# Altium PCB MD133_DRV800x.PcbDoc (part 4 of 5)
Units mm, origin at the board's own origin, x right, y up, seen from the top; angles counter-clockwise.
Board outline 152.66 x 101.89 mm, 4 copper layers (Top Layer, Mid-Layer 1, Mid-Layer 2, Bottom Layer), stack 2.355 mm thick; 306 components, 166 nets, 1010 pads, 1623 vias.
Unrouted connection lines stored in the file: 4.
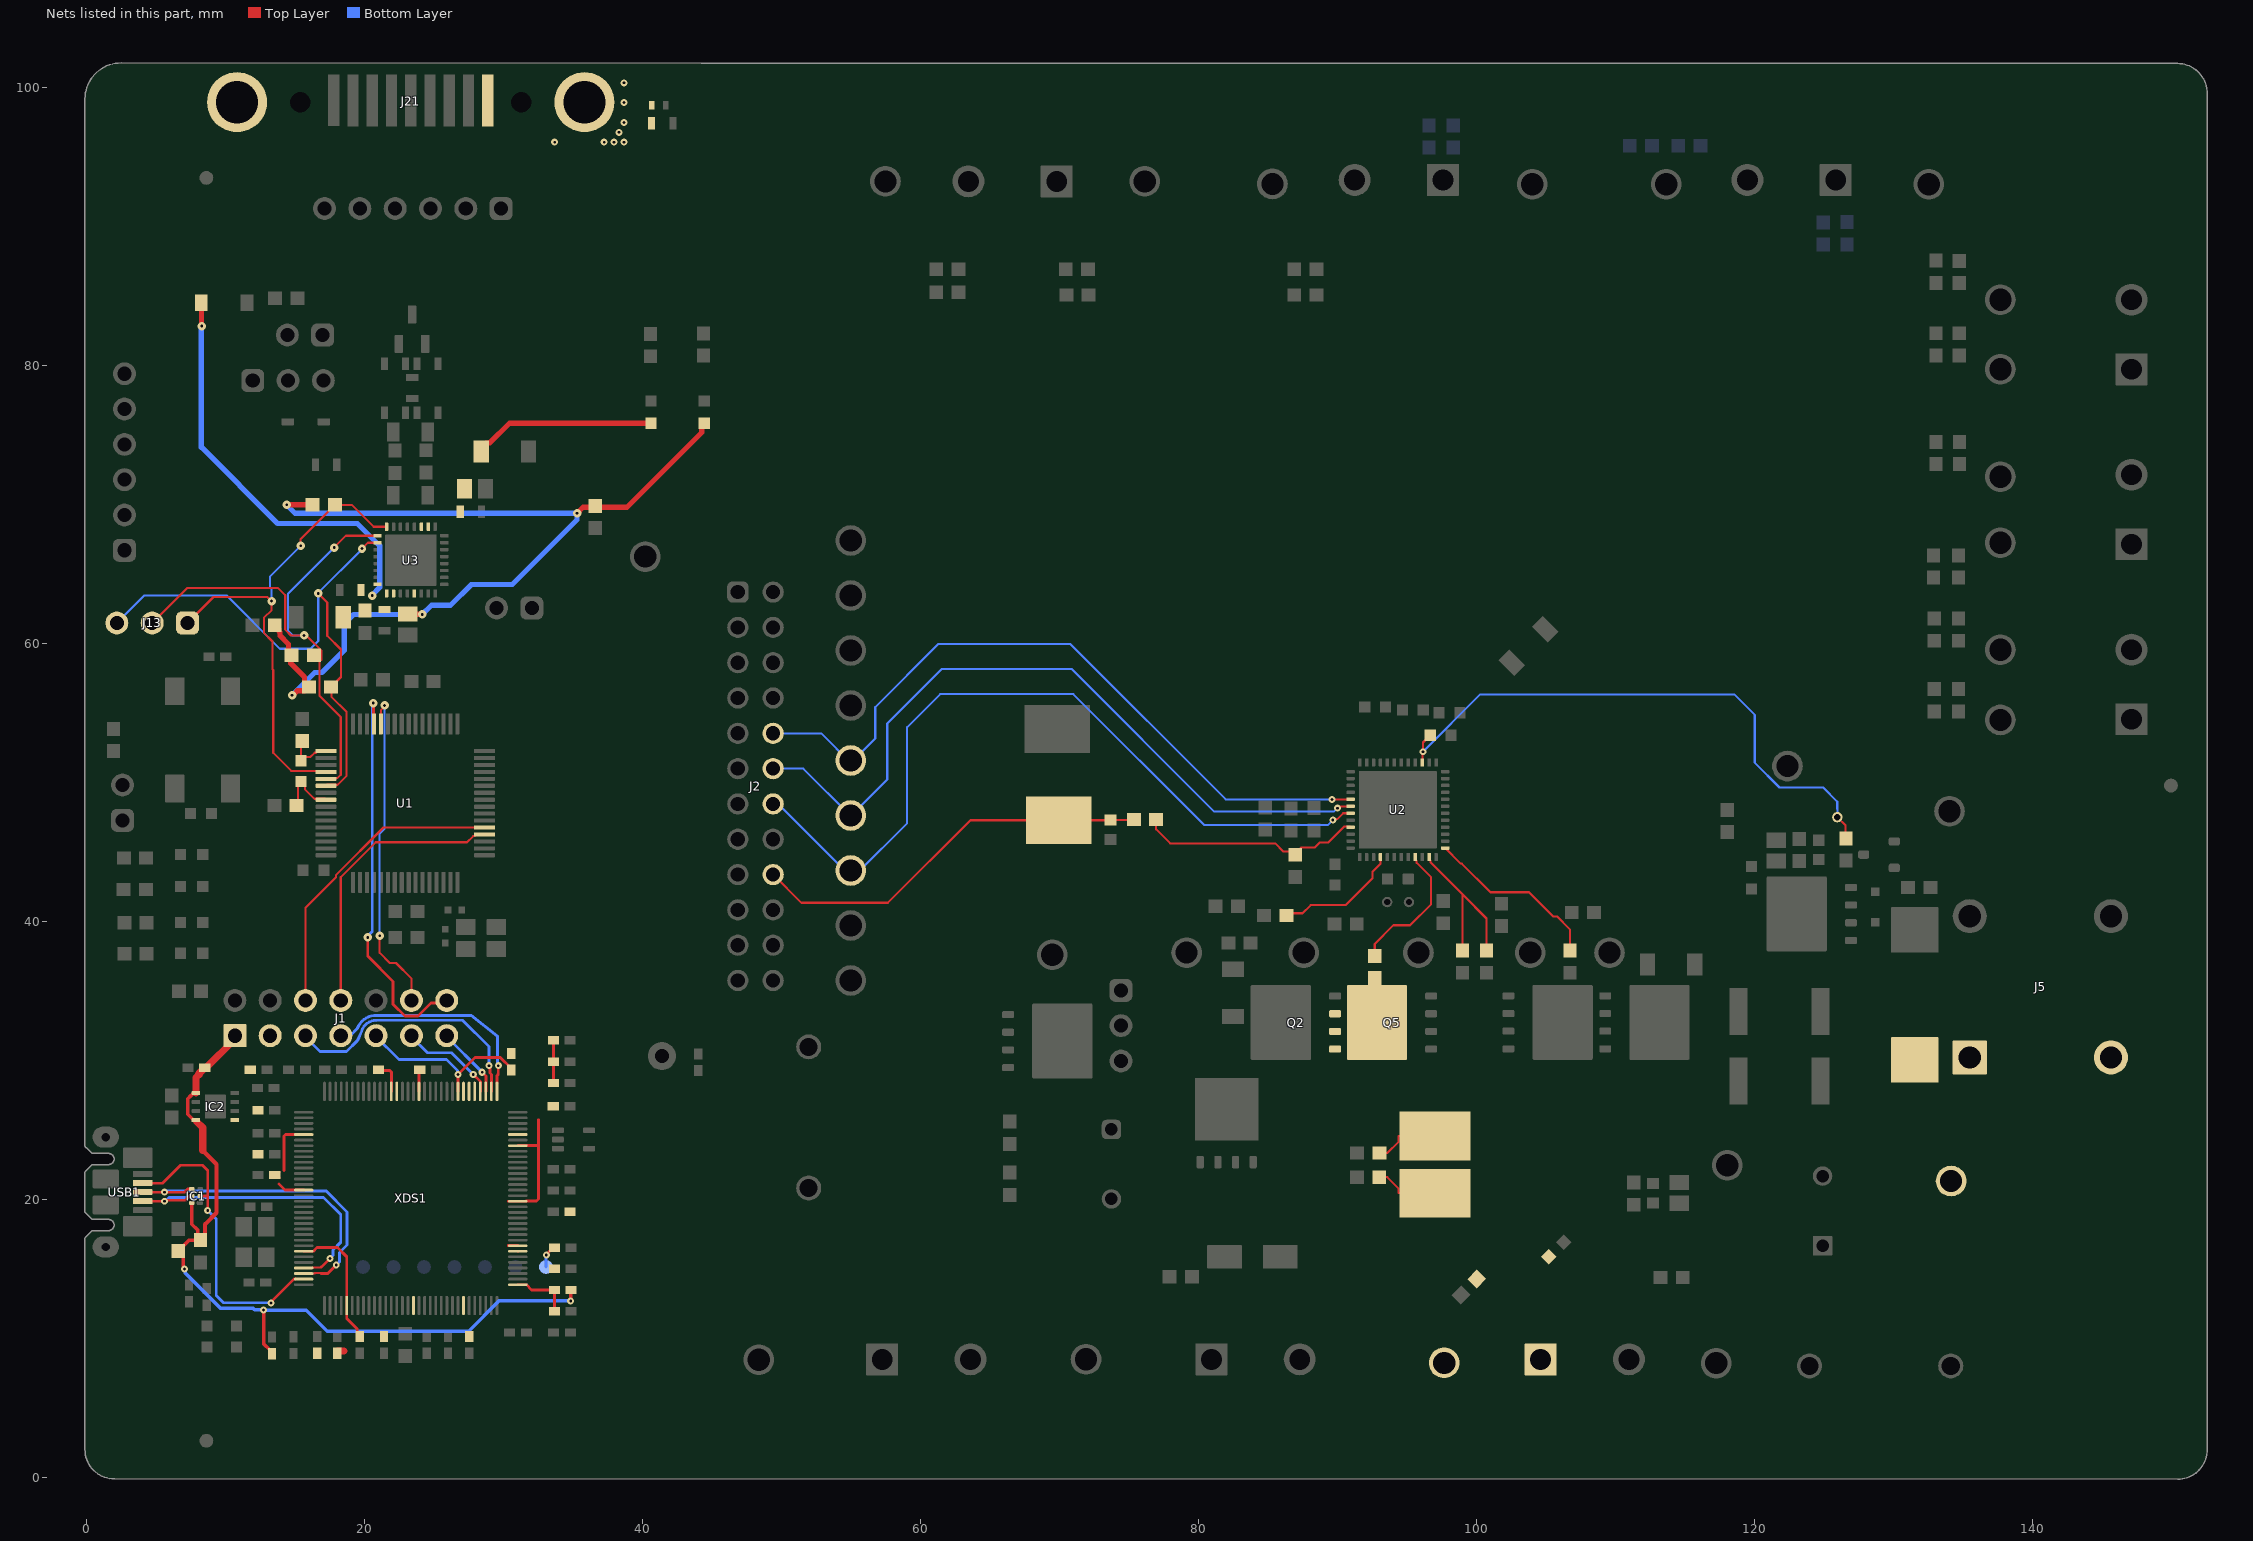
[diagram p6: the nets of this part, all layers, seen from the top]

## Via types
v1: diameter 0.5, hole 0.2, Top Layer to Bottom Layer, tented both sides, 1483 vias
v2: diameter 0.61, hole 0.2, Top Layer to Bottom Layer, tented both sides, 58 vias
v3: diameter 0.508, hole 0.203, Top Layer to Bottom Layer, tented both sides, 46 vias
v4: diameter 0.5, hole 0.2, Top Layer to Bottom Layer, 16 vias
v5: diameter 0.711, hole 0.356, Top Layer to Bottom Layer, tented both sides, 10 vias
v6: diameter 0.61, hole 0.203, Top Layer to Bottom Layer, tented both sides, 5 vias
v7: diameter 5, hole 4.3, Top Layer to Bottom Layer, 3 vias
v8: diameter 5, hole 4.5, Top Layer to Bottom Layer, 1 vias
v9: diameter 0.864, hole 0.406, Top Layer to Bottom Layer, tented both sides, 1 vias

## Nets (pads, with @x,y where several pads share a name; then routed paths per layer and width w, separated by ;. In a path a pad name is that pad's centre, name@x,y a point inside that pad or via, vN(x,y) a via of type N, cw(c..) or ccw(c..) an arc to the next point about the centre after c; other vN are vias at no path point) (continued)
SCLK: J2.14 TP15.1 U2.19 | length 58
  Top Layer w0.152: v1(89.637,47.303) 89.704,47.37 89.967,47.37 90.386,47.789 U2.19@90.915,47.789
  Bottom Layer w0.152: J2.14@49.378,48.461 49.75,48.461 50.113,48.098 50.115,48.098 54.679,43.534 54.958,43.534 55.014,43.59 TP15.1@55.014,43.987 ; TP15.1@54.958,43.59 TP15.1@54.958,43.987 ; TP15.1@55.014,43.534 55.467,43.534 59.013,47.079 59.013,53.984 61.392,56.363 70.973,56.363 80.402,46.934 89.268,46.934 v1(89.637,47.303)
SDI: J2.10 TP13.1 U2.17 | length 51.9
  Top Layer w0.152: v1(89.569,48.789) U2.17@90.915,48.789
  Bottom Layer w0.152: J2.10@49.378,53.541 52.825,53.541 54.958,51.408 56.723,53.172 56.723,55.427 61.265,59.969 70.743,59.969 81.924,48.789 v1(89.569,48.789)
SDO: J2.12 TP14.1 U2.18 | length 54.1
  Top Layer w0.152: v1(89.97,48.154) 90.064,48.154 90.199,48.289 U2.18@90.915,48.289
  Bottom Layer w0.152: J2.12@49.378,51.001 51.555,51.001 54.958,47.598 57.582,50.221 57.582,54.247 61.501,58.166 70.858,58.166 81.115,47.909 89.707,47.909 89.951,48.154 v1(89.97,48.154)
SH1: R37.2 U2.37 | length 13
  Top Layer w0.152: U2.37@97.715,45.289 98.84,44.164 98.921,44.164 100.979,42.106 103.753,42.106 105.498,40.36 105.768,40.36 106.689,39.44 R37.2@106.689,37.815
SH2: R38.2 U2.33 | length 10.2
  Top Layer w0.152: R38.2@92.65,37.242 92.65,38.387 93.995,39.733 95.187,39.733 96.707,41.253 96.707,43.188 95.664,44.232 95.664,44.365 95.565,44.464 U2.33@95.565,44.639
SH_HS: R45.2 U2.28 | length 9.1
  Top Layer w0.152: R45.2@86.294,40.437 86.453,40.596 87.454,40.596 88.043,41.184 90.55,41.184 92.489,43.122 92.489,43.574 93.065,44.15 U2.28@93.065,44.639
SHIELD_GND: C85.1 J21.5 J21.10 J21.11 R72.2
  other v1: 33.665,96.064 37.221,96.064 37.932,96.064 38.644,96.064 38.288,96.775 38.644,97.487 38.644,98.909 38.644,100.331
SL: R41.2 R42.2 U2.35 | length 12.9
  Top Layer w0.152: U2.35@96.565,44.639 96.565,44.464 96.662,44.367 96.662,44.254 98.974,41.942 ; R41.2@98.974,37.815 98.974,41.942 ; R42.2@100.694,37.815 100.694,40.222 98.974,41.942 ; R42.2@100.844,37.99 100.869,37.99 R42.2@101.006,38.127
  Top Layer w0.254: R41.2@99.141,38.106 R41.2@99.141,38.131
SNS_N: C40.1 C42.2 J4.1 R36.1 R58.2 TP24.1 | length 4.8
  Top Layer w0.152: R58.2@93.038,21.678 R58.2@92.974,21.614 93.551,21.614 94.375,20.789 94.375,20.468 R36.1@97.001,20.468
SNS_P: Q2.1 Q2.2 Q2.3 Q5.5 Q5.6 Q5.7 Q5.8 Q5.9@92.81,32.734 R36.2 R38.1 R52.2 | length 4.8
  Top Layer w0.152: R52.2@92.984,23.353 93.56,23.353 94.375,24.167 94.375,24.578 R36.2@97.001,24.578
SO: C63.1 J2.18 R53.1 TP17.1 | length 29.4
  Top Layer w0.152: J2.18@49.378,43.381 51.408,41.35 57.632,41.35 63.57,47.289 TP17.1@69.912,47.289 C63.1@73.626,47.289 ; C63.1@73.636,47.3 73.64,47.303 R53.1@74.867,47.303
  Bottom Layer w0.152: J2.18@49.378,42.783 J2.18@49.378,43.381
SO_P: C86.1 R53.2 U2.21 | length 16.1
  Top Layer w0.152: R53.2@76.928,47.344 76.928,46.642 77.944,45.627 85.494,45.627 86.088,45.032 87.07,45.032 87.369,45.331 88.338,45.331 88.691,45.684 89.309,45.684 90.476,46.85 90.602,46.85 90.614,46.838 90.866,46.838 U2.21@90.915,46.789
SWCLK: J1.14 U1.13 | length 29.1
  Top Layer w0.203: v2(20.217,38.862) 20.217,37.525 22.044,35.699 22.044,34.051 22.892,33.203 23.825,33.203 24.768,34.147 25.715,34.147 J1.14@25.898,34.33 ; v2(20.607,55.718) 20.635,55.691 20.635,54.241 U1.13@20.662,54.214
  Bottom Layer w0.203: v2(20.217,38.862) 20.217,38.972 20.539,39.293 20.539,55.65 v2(20.607,55.718) ; J1.14@25.898,34.33 J1.14@26.101,34.533
SWDIO: J1.12 U1.12 | length 24
  Top Layer w0.152: v2(21.073,38.972) 21.073,37.752 21.805,37.02 22.25,37.02 23.358,35.912 J1.12@23.358,34.33 ; U1.12@21.162,54.214 21.164,54.216 21.164,55.193 21.426,55.455 v2(21.426,55.551)
  Bottom Layer w0.152: v2(21.073,38.972) 21.073,46.321 21.426,46.673 v2(21.426,55.551)
UART1_RX: J1.6 U1.53 | length 22
  Top Layer w0.152: J1.6@15.738,34.33 15.738,40.984 17.926,43.171 17.926,43.338 21.352,46.764 U1.53@28.612,46.764
UART1_TX: J1.8 U1.52 | length 20.5
  Top Layer w0.152: J1.8@18.278,34.33 18.278,43.192 20.79,45.703 27.357,45.703 27.796,46.143 27.891,46.143 28.012,46.264 U1.52@28.612,46.264
VBAT: F1.2 J5.1 TP21.1
VBUS_DETECT: R1.2 R3.2 XDS1.1 | length 4.3
  Top Layer w0.203: XDS1.1@31.007,13.88 31.623,13.88 32.004,13.499 R1.2@33.644,13.499 R3.2@33.644,11.976
VCC1: C75.1 D6.2 R21.2 R43.2 R67.2 R73.2 R74.2 U3.13 | length 70.5
  Top Layer w0.381: R21.2@13.423,61.286 13.573,61.286 13.833,61.026 13.833,60.872 13.902,60.803 13.902,60.565 14.52,59.947 14.52,59.377 R73.2@14.67,59.226 ; v2(14.39,69.975) R74.2@16.252,69.975 ; R73.2@14.745,59.151 R73.2@14.67,59.226 ; v2(14.768,56.283) 14.83,56.283 15.142,56.594 15.669,56.594 15.903,56.829 15.903,56.879 15.669,57.113 15.669,57.588 14.67,58.587 R73.2@14.67,59.226 ; C75.1@23.108,62.118 23.122,62.104 24.118,62.104 v2(24.131,62.09) ; v2(35.277,69.364) 35.713,69.8 38.866,69.8 44.243,75.177 44.243,75.671 D6.2@44.42,75.847
  Bottom Layer w0.381: v2(14.39,69.975) 15.002,69.364 v2(35.277,69.364) 35.262,69.349 35.262,68.902 30.613,64.253 27.668,64.253 26.171,62.756 24.797,62.756 v2(24.131,62.09) 19.199,62.09 18.517,61.407 18.517,59.507 16.926,57.917 16.403,57.917 v2(14.768,56.283)
VCC2: C78.1 C79.1 C83.1 D7.2 U3.26 U3.27 | length 13.2
  Top Layer w0.381: C78.1@28.378,73.81 28.378,74.059 28.737,74.419 28.987,74.419 30.415,75.847 D7.2@40.604,75.847
VCP: C46.1 R32.1 TP30.1 U2.3 | length 42
  Top Layer w0.152: U2.3@96.065,51.439 96.092,51.466 96.092,52.189 v1(96.12,52.216) 96.12,52.878 C46.1@96.647,53.405 ; TP30.1@125.927,47.506 126.521,46.912 R32.1@126.521,45.826
  Bottom Layer w0.152: v1(96.12,52.216) 100.247,56.343 118.51,56.343 119.986,54.867 119.986,51.432 121.772,49.646 124.905,49.646 125.927,48.624 TP30.1@125.927,47.506
VREF_N: C27.1 R27.2 U1.17 | length 3.3
  Top Layer w0.152: R27.2@15.391,52.814 15.428,52.776 C27.1@15.428,51.564 15.71,51.846 16.099,51.846 16.396,52.143 16.491,52.143 16.612,52.264 U1.17@17.212,52.264
VREF_P: C27.2 R26.2 U1.24 | length 3.9
  Top Layer w0.152: R26.2@15.19,48.764 15.19,49.826 C27.2@15.428,50.064 15.69,49.802 15.69,49.525 16.377,48.838 17.138,48.838 U1.24@17.212,48.764
VSUP: C74.1 C76.1 C77.1 D8.2 R64.1 U3.8 U3.9 U3.10 | length 30
  Top Layer w0.381: D8.2@8.248,84.513 8.265,84.497 8.265,82.855 v2(8.281,82.838)
  Bottom Layer w0.381: v2(8.281,82.838) 8.248,82.806 8.248,74.125 13.733,68.64 19.463,68.64 21.073,67.03 21.073,64.036 20.545,63.508 v2(20.545,63.446)
WAKE1: J13.3 R43.1 U1.22 U3.2 | length 42.7
  Top Layer w0.152: v2(16.652,63.603) 17.302,62.953 17.302,60.56 18.292,59.57 18.292,57.593 18.002,57.302 18.002,57.277 17.603,56.879 17.603,56.175 18.701,55.077 18.701,50.492 18.048,49.838 17.286,49.838 U1.22@17.212,49.764 ; v2(19.802,66.834) 20.221,67.253 U3.2@20.92,67.253
  Bottom Layer w0.152: J13.3@2.169,61.476 4.154,63.461 10.057,63.461 13.892,59.626 16.095,59.626 16.652,60.183 v2(16.652,63.603) 16.652,63.643 19.802,66.793 v2(19.802,66.834)
WAKE2: J13.2 R73.1 U1.21 U3.1 | length 39.8
  Top Layer w0.152: J13.2@4.709,61.476 7.214,63.982 13.772,63.982 14.279,63.475 14.279,60.998 14.697,60.581 v2(15.636,60.581) 15.724,60.493 15.878,60.493 16.895,59.476 16.895,58.826 ; R73.1@16.745,59.151 16.745,56.238 18.273,54.71 18.273,50.563 18.048,50.338 17.286,50.338 U1.21@17.212,50.264 ; v2(17.812,66.901) 17.812,66.922 18.642,67.753 U3.1@20.92,67.753
  Bottom Layer w0.152: v2(15.636,60.581) 14.778,60.581 14.778,60.61 14.49,60.898 14.49,63.6 17.79,66.901 v2(17.812,66.901)
WAKE3: J13.1 R74.1 U1.20 U3.32 | length 36
  Top Layer w0.152: J13.1@7.249,61.476 9.121,63.348 12.984,63.348 13.277,63.055 v2(13.302,63.055) 13.302,62.405 12.747,61.85 12.747,60.771 13.369,60.149 13.369,58.162 13.423,58.108 13.423,52.131 14.716,50.838 17.138,50.838 U1.20@17.212,50.764 ; v2(15.391,67.03) 15.391,67.515 17.428,69.553 17.428,69.578 17.827,69.977 19.072,69.977 20.645,68.403 U3.32@21.57,68.403
  Bottom Layer w0.152: v2(13.302,63.055) 13.302,63.948 13.19,64.06 13.19,64.829 v2(15.391,67.03)
XDS_ID: IC1.2 USB1.4 XDS1.95 | length 21.8
  Top Layer w0.203: USB1.4@4.03,21.195 4.045,21.18 5.455,21.18 6.743,22.468 8.337,22.468 8.702,22.103 8.702,20.258 ; IC1.2@8.164,20.258 8.702,20.258 ; v3(8.702,19.217) 8.702,20.258 ; v3(13.249,12.562) 13.288,12.601 13.288,12.661 14.905,14.279 XDS1.95@15.009,14.279
  Bottom Layer w0.203: v3(8.702,19.217) 9.32,18.599 9.32,13.095 9.837,12.578 13.233,12.578 v3(13.249,12.562)
XDS_RESET_OUT: J1.9 R4.1 XDS1.40 | length 13.2
  Top Layer w0.203: v3(26.717,29.002) 27.93,30.215 29.749,30.215 30.545,29.419 R4.1@30.545,29.319 ; XDS1.40@26.718,27.789 v3@26.718,29.002
  Bottom Layer w0.203: J1.9@20.789,31.741 22.457,30.074 25.891,30.074 26.678,29.286 26.678,29.041 v3(26.717,29.002)
XDS_RXD: J1.7 XDS1.33 | length 17.2
  Top Layer w0.203: XDS1.33@29.507,28.379 29.507,28.912 29.607,29.011 v3(29.607,29.631)
  Bottom Layer w0.203: J1.7@18.273,31.815 18.964,31.815 19.471,32.323 ; v3(29.607,29.631) 29.548,29.689 29.548,31.745 27.632,33.25 20.666,33.25 20.522,33.22 ; 19.471,32.322 cw(c20.813,31.815) 20.269,33.143 ; 19.471,32.323 cw(c20.813,31.815) 19.477,32.337 cw(c20.813,31.815) 20.269,33.143 ; 20.269,33.143 20.273,33.144 20.322,33.165 ; 20.322,33.165 cw(c20.4,32.977) 20.352,33.174 ; 20.322,33.165 cw(c20.4,32.977) 20.352,33.174 ; 20.352,33.174 20.395,33.188 ; 20.395,33.188 cw(c20.813,31.815) 20.522,33.22 ; 20.395,33.188 cw(c20.813,31.815) 20.522,33.22
XDS_TCK_SWDCLK: J1.13 XDS1.35 | length 5.1
  Top Layer w0.203: v3(28.45,29.16) 28.719,28.891 XDS1.35@28.719,27.788
  Bottom Layer w0.203: J1.13@25.869,31.741 v3(28.45,29.16)
XDS_TDI: XDS1.38
XDS_TDO_SWO: XDS1.37
XDS_TMS_SWDIO: J1.11 XDS1.36 | length 7
  Top Layer w0.203: v3(27.805,29.002) 28.317,28.49 28.317,27.79 XDS1.36@28.319,27.788
  Bottom Layer w0.203: J1.11@23.329,31.741 24.51,30.56 26.248,30.56 v3(27.805,29.002)
XDS_TXD: J1.5 XDS1.34 | length 20.2
  Top Layer w0.203: v3(28.946,29.631) 29.005,29.572 29.005,29.109 29.119,28.994 XDS1.34@29.119,27.788
  Bottom Layer w0.203: J1.5@15.709,31.741 16.788,30.662 18.696,30.662 19.459,31.426 19.519,31.485 19.781,32.129 ; v3(28.946,29.631) 28.946,31 27.052,32.894 20.813,32.894 ; 19.781,32.129 cw(c20.813,31.815) 20.813,32.894 ; 19.781,32.129 cw(c20.813,31.815) 20.813,32.894
XDS_USB_D_N: IC1.5 USB1.2 XDS1.93 | length 22.5
  Top Layer w0.152: XDS1.93@15.607,15.087 16.215,15.087 16.253,15.124 16.842,15.124 16.868,15.15
  Top Layer w0.203: USB1.2@4.184,19.88 5.593,19.88 v1(5.594,19.879) 5.668,19.953 7.104,19.953 7.409,20.258 IC1.5@7.564,20.258 ; 16.868,15.15 16.878,15.15 v1(17.491,15.763)
  Bottom Layer w0.203: v1(5.594,19.879) 5.654,19.879 5.932,20.157 17.043,20.157 18.271,18.929 18.271,16.927 17.726,16.382 17.726,15.998 v1(17.491,15.763)
XDS_USB_D_P: IC1.4 USB1.3 XDS1.94 | length 24
  Top Layer w0.152: XDS1.94@15.607,14.68 16.384,14.68 16.421,14.718 16.842,14.718 16.868,14.693
  Top Layer w0.203: USB1.3@4.184,20.53 v1(5.594,20.531) v1(5.594,20.531) 7.036,20.531 7.263,20.758 IC1.4@7.564,20.758 ; 16.868,14.693 17.343,14.693 v1(17.952,15.302)
  Bottom Layer w0.203: v1(5.594,20.531) 5.676,20.614 17.232,20.614 18.728,19.118 18.728,16.738 18.183,16.193 18.183,15.533 v1(17.952,15.302)
XDS_VBUS: C1.1 C3.1 IC1.6 IC2.5 IC2.8 J1.1 R1.1 R5.2 R13.1 | length 58.3
  Top Layer w0.254: v3@6.93,15.166 6.93,15.94 R5.2@6.582,16.288 6.582,16.313 7.357,17.088 C1.1@8.169,17.088 ; IC1.6@7.553,19.726 7.553,18.238 7.971,17.82 7.971,17.461 C1.1@8.33,17.461 ; IC2.8@7.654,25.749 7.274,26.129 7.274,27.262 7.467,27.455 7.493,27.455 7.708,27.671 IC2.5@7.853,27.671 ; v3(12.716,12.054) 12.748,12.022 12.748,9.593 13.155,9.187 13.155,9.082 R13.1@13.327,8.909 ; v3(34.814,12.714) 34.814,13.469 R1.1@34.844,13.499
  Top Layer w0.305: C1.1@8.177,17.109 8.504,17.436 8.504,18.219 9.337,19.052 9.337,22.544 8.347,23.535
  Top Layer w0.508: IC2.5@7.853,27.671 7.853,28.77 8.096,29.013 8.096,29.088 8.344,29.336 8.344,29.436 8.39,29.482 8.59,29.482 10.629,31.521 J1.1@10.629,31.741 ; IC2.8@7.899,25.622 8.347,25.174 8.347,23.535
  Bottom Layer w0.254: v3@7.001,15.051 7.075,14.977 7.075,14.727 9.605,12.197 11.954,12.197 12.071,12.079 12.69,12.079 12.741,12.029 15.797,12.029 17.295,10.53 27.473,10.53 29.657,12.714 v3(34.814,12.714)
  other v3: 7.026,15
XDS_VCC: C4.1 C5.1 C6.1 C7.1 C8.1 C9.1 C10.1 C13.1 C14.1 IC2.1 J1.3 R4.2 R7.1 R8.1 R9.2 R10.2 R11.2 R12.2 R14.2 R17.2 R18.2 TP7.1 XDS1.7 XDS1.8 XDS1.16 XDS1.26 XDS1.28 XDS1.39 XDS1.47 XDS1.51 XDS1.52 XDS1.69 XDS1.79 XDS1.90 XDS1.101 XDS1.113 XDS1.122 | length 35.7
  Top Layer w0.203: C5.1@13.529,21.772 C5.1@13.629,21.772 ; 13.827,21.128 14.267,20.688 XDS1.79@15.619,20.688 ; C5.1@13.827,21.574 C5.1@13.629,21.772 ; C5.1@13.827,21.971 C5.1@13.629,21.772 ; 14.183,22.09 14.183,24.561 14.302,24.68 XDS1.69@15.009,24.68 ; XDS1.90@15.607,16.28 16.308,16.28 16.577,16.55 18.05,16.55 18.707,15.892 XDS1.101@18.707,12.38 18.707,11.447 19.459,10.696 19.459,10.328 C9.1@19.637,10.149 ; C7.1@20.942,29.482 21.14,29.283 21.798,29.283 21.917,29.164 21.917,27.79 XDS1.52@21.919,27.788 ; XDS1.47@23.907,27.78 23.907,29.287 C6.1@23.957,29.336 ; C4.1@27.519,10.149 C4.1@27.519,10.249 ; XDS1.8@30.317,16.69 31.017,16.69 XDS1.8@31.019,16.688 ; XDS1.16@30.317,19.886 31.613,19.886 31.617,19.89 32.336,19.89 32.489,20.043 32.489,25.743 ; R4.2@30.418,30.392 R4.2@30.545,30.519 ; XDS1.7@31.017,16.286 XDS1.7@31.019,16.288 ; XDS1.26@31.019,23.888 31.615,23.888 31.617,23.89 32.489,23.89 ; v3(33.061,16.016) 33.061,16.062 33.544,16.545 C13.1@33.644,16.545 ; C14.1@33.456,26.709 C14.1@33.556,26.709 ; R11.2@33.568,31.452 R10.2@33.568,29.919 R9.2@33.568,28.386 R9.2@33.668,28.386
  Top Layer w0.508: R8.1@18.011,8.949 18.011,9.049 18.057,9.095 18.509,9.095 ; C9.1@19.637,10.049 C9.1@19.637,10.149
  Bottom Layer w0.203: TP7.1@33.036,15.153 33.048,15.165 33.048,16.004 v3(33.061,16.016)
pads on no net: FID1.1 FID2.1 FID3.1 H1.0 H2.0 H3.0 H4.0 IC2.2 IC2.3 IC2.6 IC2.7 IC3.2 IC3.4 IC3.5 J21.1 J21.4 J21.9 J21.MH Q2.9@85.213,31.404 Q2.9@85.213,32.734 Q2.9@85.213,34.064 Q2.9@86.228,32.734 Q2.9@86.363,31.404 Q2.9@86.363,32.734 Q2.9@86.363,34.064 Q2.9@87.513,31.404 Q2.9@87.513,32.734 Q2.9@87.513,34.064 Q2.9@87.808,30.361 Q2.9@87.808,35.106 Q3.9@111.224,30.377 Q3.9@111.224,35.122 Q3.9@111.519,31.42 Q3.9@111.519,32.75 Q3.9@111.519,34.08 Q3.9@112.669,31.42 Q3.9@112.669,32.75 Q3.9@112.669,34.08 Q3.9@112.804,32.75 Q3.9@113.819,31.42 Q3.9@113.819,32.75 Q3.9@113.819,34.08 Q4.9@122.326,39.218 Q4.9@122.326,40.548 Q4.9@122.326,41.878 Q4.9@123.341,40.548 Q4.9@123.476,39.218 Q4.9@123.476,40.548 Q4.9@123.476,41.878 Q4.9@124.626,39.218 Q4.9@124.626,40.548 Q4.9@124.626,41.878 Q4.9@124.921,38.176 Q4.9@124.921,42.921 Q5.9@92.125,31.404 Q5.9@92.125,32.734 Q5.9@92.125,34.064 Q5.9@93.14,32.734 Q5.9@93.275,31.404 Q5.9@93.275,32.734 Q5.9@93.275,34.064 Q5.9@94.72,30.361 Q5.9@94.72,35.106 Q5.9@94.425,31.404 Q5.9@94.425,32.734 Q5.9@94.425,34.064 Q6.9@104.257,30.377 Q6.9@104.257,35.122 Q6.9@104.552,31.42 Q6.9@104.552,32.75 Q6.9@104.552,34.08 Q6.9@105.702,31.42 Q6.9@105.702,32.75 Q6.9@105.702,34.08 Q6.9@105.837,32.75 Q6.9@106.852,31.42 Q6.9@106.852,32.75 Q6.9@106.852,34.08 Q7.9@80.556,25.112 Q7.9@80.556,26.892 Q7.9@82.006,25.112 Q7.9@82.006,26.042 Q7.9@82.006,26.892 Q7.9@83.456,25.112 Q7.9@83.456,26.892 Q8.9@68.27,29.031 Q8.9@68.27,33.776 Q8.9@68.565,30.074 Q8.9@68.565,31.404 Q8.9@68.565,32.734 Q8.9@69.85,31.404 Q8.9@69.715,30.074 Q8.9@69.715,31.404 Q8.9@69.715,32.734 Q8.9@70.865,30.074 Q8.9@70.865,31.404 Q8.9@70.865,32.734 SH-J1.0 SH-J2.0 SH-J3.0 SH-J4.0 SH-J5.0 SH-J6.0 SH-J7.0 SH-J8.0 SH-J9.0 SH-J10.0 SH-J11.0 SH-J12.0 SH-J13.0 SH-J14.0 SH-J15.0 SH-J16.0 SH-J17.0 SH-J18.0 SH-J19.0 SH-J20.0 SH-J21.0 U1.2 U1.7 U1.11 U1.15 U1.18 U1.19 U1.23 U1.25 U1.28 U1.31 U1.33 U1.34 U1.36 U1.37 U1.39 U1.42 U1.44 U1.47 U1.49 U1.50 U1.51 U1.55 U1.62 U1.63 U1.64 U3.3 U3.11 U3.12 XDS1.2 XDS1.5 XDS1.6 XDS1.11 XDS1.12 XDS1.13 XDS1.14 XDS1.15 XDS1.18 XDS1.19 XDS1.20 XDS1.21 XDS1.22 XDS1.23 XDS1.24 XDS1.25 XDS1.27 XDS1.29 XDS1.30 XDS1.31 XDS1.32 XDS1.41 XDS1.43 XDS1.44 XDS1.45 XDS1.46 XDS1.49 XDS1.50 XDS1.53 XDS1.54 XDS1.56 XDS1.57 XDS1.65 XDS1.67 XDS1.71 XDS1.72 XDS1.73 XDS1.74 XDS1.75 XDS1.76 XDS1.77 XDS1.78 XDS1.81 XDS1.82 XDS1.83 XDS1.84 XDS1.85 XDS1.86 XDS1.91 XDS1.92 XDS1.102 XDS1.103 XDS1.104 XDS1.105 XDS1.106 XDS1.107 XDS1.108 XDS1.109 XDS1.110 XDS1.111 XDS1.112 XDS1.116 XDS1.117 XDS1.118 XDS1.119 XDS1.121 XDS1.123 XDS1.124 XDS1.125 XDS1.126 XDS1.127 XDS1.128
copper on no net:
  other v3: 16.754,14.111 16.729,15.864 6.645,19.445 6.645,21.503

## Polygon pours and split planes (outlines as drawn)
ECDRV on Top Layer "TOP_LAYER_ECDRV_P352" (solid, remove dead copper, pour order 352): 67.095,24.741 65.715,24.741 65.715,21.392 65.771,21.336 65.811,21.376 66.966,21.376 66.966,24.613
GND on Top Layer "TOP_LAYER_GND_P366" (solid, remove dead copper, pour order 366): 0,101.6 0,0 152.4,0 152.4,101.6
OUT5 on Top Layer "TOP_LAYER_OUT5_P325" (solid, remove dead copper, pour order 325): 91.141,54.91 91.284,54.767 91.63,54.767 92.208,54.189 93.275,53.122 93.275,51.057 93.269,51.063 92.733,51.063 92.733,52.278 91.505,53.506 90.594,53.506 87.757,56.343 87.757,91.066 86.754,92.069 86.659,91.973 84.125,91.973 84.125,94.38 84.22,94.475 91.707,94.475 92.461,93.721 92.461,92.461 91.141,91.141
PVDD on Top Layer "TOP_LAYER_PVDD_P053" (solid, remove dead copper, pour order 330): 120.396,27.078 120.41,27.092 120.41,35.464 120.396,36.905 120.396,42.843 101.327,61.911 94.365,61.911 93.866,61.911 92.741,60.786 92.741,54.235 93.457,53.519 93.457,51.057 93.735,51.057 94.565,51.887 94.565,56.134 98.79,56.134 98.79,54.515 96.32,52.044 96.32,51.093 96.33,51.083 96.344,51.097 96.843,51.097 96.843,51.827 97.13,52.114 98.417,52.114 99.246,52.943 100.272,52.943 102.226,54.897 102.226,54.911 102.85,55.535 103.493,55.535 104.524,54.504 104.524,52.193 101.734,49.402 97.358,49.402 97.358,49.316 97.411,49.263 97.411,47.855 104.016,47.855 113.716,38.156 113.741,36.633 112.966,35.858 110.381,35.858 110.381,20.586 120.396,20.586
OUT7 on Top Layer "TOP_LAYER_OUT7_P350" (solid, remove dead copper, pour order 350): 132.361,86.487 148.209,86.487 148.463,86.233 148.463,83.533 136.722,83.533 135.051,85.205 132.385,85.205
OUT12 on Top Layer "TOP_LAYER_OUT12_P346" (solid, remove dead copper, pour order 346): 132.226,55.727 148.529,55.727 148.775,55.48 148.775,52.995 137.049,52.995 135.911,54.133 135.911,54.177 132.183,54.177
OUT11 on Top Layer "OUT11" (solid, remove dead copper, pour order 340): 148.895,60.952 148.819,60.876 148.819,58.287 138.877,58.287 136.749,58.287 135.591,59.444 131.972,59.444 131.972,60.952
OUT10 on Top Layer "TOP_LAYER_OUT10_P338" (solid, remove dead copper, pour order 338): 138.674,68.516 148.777,68.516 148.777,65.904 148.819,65.862 148.493,65.537 137.607,65.537 137.461,65.545 131.976,65.545 131.972,67.099 135.84,67.099 135.891,67.048 137.36,68.516
OUT9 on Top Layer "OUT9" (solid, remove dead copper, pour order 336): 148.659,73.464 148.463,73.703 132.196,73.703 132.171,71.821 135.424,71.821 136.462,70.783 138.133,70.783 148.659,70.783
OUT8 on Top Layer "TOP_LAYER_OUT8_P334" (solid, remove dead copper, pour order 334): 148.074,78.638 148.361,78.926 148.354,79.019 148.354,81.407 132.358,81.407 132.269,79.966 135.09,79.966 136.253,78.803 136.253,78.638
OUT6 on Top Layer "TOP_LAYER_OUT6_P307" (solid, remove dead copper, pour order 307): 100.609,50.364 104.235,53.99 104.235,50.636 103.27,49.671 97.358,49.671 97.358,49.897 97.398,49.936 98.435,50.364
OUT8 on Top Layer "TOP_LAYER_OUT8_P298" (solid, remove dead copper, pour order 298): 98.579,47.826 98.695,47.942 102.946,47.942 102.946,47.347 99.059,47.347
OUT11 on Top Layer "TOP_LAYER_OUT11_P302" (solid, remove dead copper, pour order 302): 98.289,46.239 98.533,46.239 98.784,46.489 99.911,45.362 106.167,45.362 106.167,44.802 99.725,44.802
OUT3 on Top Layer "TOP_LAYER_OUT3_P308" (solid, remove dead copper, pour order 308): 101.087,53.405 103.146,55.464 104.131,54.479 104.131,54.258 104.103,54.258 103.398,53.552 100.434,50.589 97.436,50.589 97.433,51.159 100.072,51.159 101.087,52.173
OUT12 on Top Layer "TOP_LAYER_OUT12_P303" (solid, remove dead copper, pour order 303): 98.136,45.718 98.909,45.718 100.395,44.232 106.925,44.232 106.925,43.747 100.107,43.747
OUT10 on Top Layer "TOP_LAYER_OUT10_P299" (solid, remove dead copper, pour order 299): 98.238,46.947 98.376,47.086 98.376,47.347 99.484,46.239 105.231,46.239 105.231,45.726 99.46,45.726
OUT9 on Top Layer "TOP_LAYER_OUT9_P296" (solid, remove dead copper, pour order 296): 98.324,47.499 98.324,47.521 98.55,47.748 99.262,47.017 103.973,47.017 103.973,46.559 99.264,46.559
OUT4 on Top Layer "TOP_LAYER_OUT4_P139" (solid, remove dead copper, pour order 306): 100.653,52.915 101.047,52.522 100.834,52.309 99.895,51.37 98.317,51.378 98.247,51.308 98.247,51.126 96.843,51.126 96.843,51.827 96.9,51.884 97.527,51.884 97.756,52.114 98.075,52.114 98.82,52.859 98.82,52.915
OUT2 on Top Layer "TOP_LAYER_OUT2_P322" (solid, remove dead copper, pour order 322): 63.652,94.475 64.607,93.52 64.607,76.515 86.172,54.656 86.371,54.457 88.813,52.015 91.755,52.015 91.755,51.054 87.097,51.054 68.53,69.621 62,76.314 62,90.995 60.73,92.266 56.828,92.266 56.515,92.578 56.515,94.463 61.987,94.463 62,94.475
OUT1 on Top Layer "TOP_LAYER_OUT1_P323" (solid, remove dead copper, pour order 323): 68.199,93.998 68.627,94.426 77.378,94.426 77.378,92.128 77.437,92.069 72.178,92.069 71.227,91.116 71.284,72.593 90.535,53.343 91.668,53.343 92.32,52.691 92.32,51.054 92.317,51.057 91.755,51.057 91.755,52.123 89.115,52.123 68.199,73.039
SHIELD_GND on Top Layer "TOP_LAYER_SHIELD_GND_P318" (solid, remove dead copper, pour order 318): 28.534,95.301 41.224,95.301 41.224,100.815 28.534,100.815
NetC82_2 on Top Layer "TOP_LAYER_NETC82_2_P294" (solid, remove dead copper, pour order 294): 22.645,79.726 22.906,79.465 22.906,78.921 23.906,78.921 23.906,79.471 24.05,79.615 24.05,80.625 22.645,80.625
VCC2 on Top Layer "TOP_LAYER_VCC2_P312" (solid, remove dead copper, pour order 312): 23.953,68.05 23.953,69.364 25.662,69.364 26.506,70.208 26.506,71.931 27.194,71.931 27.891,72.628 27.891,74.809 29.178,74.809 29.345,74.642 29.345,72.941 28.035,71.631 27.931,71.631 27.931,69.277 27.568,68.914 24.797,68.914 24.797,68.05
VCC1 on Top Layer "TOP_LAYER_VCC1_P297" (solid, remove dead copper, pour order 297): 22.308,61.568 22.308,63.124 23.37,63.124 23.37,63.936 23.744,63.936 23.744,63.132 24.519,62.357 24.519,61.568
PVDD on Top Layer "TOP_LAYER_PVDD_P300" (solid, remove dead copper, pour order 300): 18.877,59.355 18.769,59.247 18.769,56.829 20.052,56.829 20.291,57.067 20.291,58.828 20.926,59.463 20.926,61.311 19.486,61.311 18.868,60.693 18.868,59.364
VSUP on Top Layer "TOP_LAYER_VSUP_P310" (solid, remove dead copper, pour order 310): 17.837,60.89 17.837,62.89 19,62.89 19.441,63.332 19.441,64.343 21.27,64.343 21.27,64.111 21.479,63.903 22.297,63.903 22.297,62.052 21.884,61.639 19.617,61.639 18.868,60.89
DVDD on Top Layer "TOP_LAYER_DVDD_P295" (solid, remove dead copper, pour order 295): 89.148,43.373 90.284,43.373 90.284,44.162 91.101,44.979 91.29,44.979 91.29,45.479 90.53,45.479 89.774,44.723 89.261,44.723 89.261,43.373
no net on Top Layer "TOP_LAYER_NONET_P313" (solid, remove dead copper, pour order 313): 14.274,37.249 14.417,37.392 14.417,40.937 12.229,40.937 11.507,40.214 11.507,37.249
3V3_MCU on Top Layer "TOP_LAYER_3V3_MCU_P311" (solid, remove dead copper, pour order 311): 7.725,39.221 7.703,39.243 7.703,43.211 10.231,43.211 10.27,43.171 10.259,43.161 10.259,40.295 9.186,39.221 7.708,39.221
3V3_MCU on Top Layer "TOP_LAYER_3V3_MCU_P304" (solid, remove dead copper, pour order 304): 2.692,53.064 3.242,53.614 3.242,55.318 0.961,55.318 0.961,53.064
3V3_MCU on Top Layer "TOP_LAYER_3V3_MCU_P314" (solid, remove dead copper, pour order 314): 9.398,58.229 9.398,62.789 12.681,62.789 12.673,62.781 12.673,58.917 12.646,58.917 11.958,58.229
NetQ1_3 on Top Layer "TOP_LAYER_NETQ1_3_P305" (solid, remove dead copper, pour order 305): 128.075,44.526 127.502,43.952 127.502,43.207 127.502,41.878 126.152,41.878 126.152,43.181 126.126,43.207 126.126,45.101 128.249,45.101 128.249,44.526
NetC58_2 on Top Layer "TOP_LAYER_NETC58_2_P320" (solid, remove dead copper, pour order 320): 78.963,11.645 76.931,9.612 70.508,9.612 70.508,7.112 70.655,7.112 83.312,7.112 83.312,22.96 83.093,23.179 78.963,23.179
NetJ23_2 on Top Layer "TOP_LAYER_NETJ23_2_P316" (solid, remove dead copper, pour order 316): 68.145,34.228 73.048,34.228 73.713,33.564 75.307,33.564 75.667,33.204 75.667,31.5 73.223,31.5 72.644,30.921 72.644,28.644 68.145,28.644
ECFB on Top Layer "TOP_LAYER_ECFB_P327" (solid, remove dead copper, pour order 327): 58.699,6.908 58.699,6.944 65.532,13.777 65.532,30.184 66.772,30.184 66.772,34.036 61.501,34.036 60.757,33.292 60.757,15.472 56.084,10.799 47.429,10.799 47.429,6.908
SNS_P on Top Layer "TOP_LAYER_SNS_P_P319" (solid, remove dead copper, pour order 319): 90.559,28.935 90.559,27.747 94.315,23.991 94.315,22.802 99.822,22.802 99.822,27.571 99.171,28.222 95.545,28.222 94.94,28.827 94.94,36.183 93.724,36.183 93.174,36.733 90.559,36.733 90.559,34.533 89.762,33.736 89.152,33.736 89.152,30.342
GND on Top Layer "TOP_LAYER_GND_P317" (solid, remove dead copper, pour order 317): 99.525,28.525 101.512,28.525 101.512,31.099 101.88,31.468 102.836,31.468 102.836,35.65 101.616,35.65 101.6,35.667 101.6,36.905 101.598,36.908 97.821,36.908 97.821,34.681 97.232,34.092 95.452,34.092 95.462,28.525
GD_OUT1 on Top Layer "TOP_LAYER_GD_OUT1_P328" (solid, remove dead copper, pour order 328): 113.819,9.361 118.278,9.361 118.278,7.112 112.199,7.112 112.199,6.858 108.562,6.858 108.562,13.866 103.038,19.39 103.038,36.565 105.821,36.565 106.689,37.433 108.562,37.433 109.827,36.167 109.827,31.346 108.529,31.346 108.529,20.983 113.819,15.693
SNS_N on Top Layer "TOP_LAYER_SNS_N_P321" (solid, remove dead copper, pour order 321): 100.614,9.361 96.926,9.361 96.926,7.112 100.838,7.112 100.838,6.872 102.267,6.858 106.172,6.858 106.172,15.799 99.499,22.472 94.455,22.472 94.455,18.508 100.614,12.914
PVDD on Top Layer "TOP_LAYER_PVDD_P324" (solid, remove dead copper, pour order 324): 73.127,31.166 77.616,31.166 77.616,34.142 83.716,34.142 83.716,35.858 88.502,35.858 88.502,24.155 77.616,24.155 73.156,24.155 73.127,24.184
NetQ1_1 on Top Layer "TOP_LAYER_NETQ1_1_P301" (solid, remove dead copper, pour order 301): 130.131,42.944 129.549,43.526 129.549,44.184 131.826,44.184 131.826,41.727 130.131,41.727
NetD5_2 on Top Layer "TOP_LAYER_NETD5_2_P309" (solid, remove dead copper, pour order 309): 127.761,42.997 127.761,44.002 129.013,45.254 129.013,46.197 131.351,46.197 131.351,44.314 130.1,44.314 129.865,44.048 129.865,41.727 127.727,41.727 127.727,42.997
PI_IN on Top Layer "TOP_LAYER_PI_IN_P326" (solid, remove dead copper, pour order 326): 120.808,38.097 122.047,36.858 122.047,25.039 120.788,23.78 120.788,20.586 127.938,20.586 127.938,37.344 125.315,37.344 125.315,45.151 120.808,45.151
NetD5_1 on Top Layer "TOP_LAYER_NETD5_1_P315" (solid, remove dead copper, pour order 315): 126.126,41.504 133.604,41.504 133.604,37.558 126.126,37.558
VBAT on Top Layer "TOP_LAYER_VBAT_P329" (solid, remove dead copper, pour order 329): 142.584,18.796 128.413,18.796 128.413,32.258 151.982,32.258 151.982,18.796
XDS_VCC on Top Layer "TOP_LAYER_XDS_VCC_P331" (solid, remove dead copper, pour order 331): 8.504,2.889 9.526,1.945 10.085,1.945 33.378,1.945 34.8,3.367 34.8,8.487 38.242,8.487 39.32,9.565 39.218,9.666 39.218,32.399 8.504,32.399
OUT8 on Mid-Layer 2 "MID-LAYER_2_NONET_P152" (solid, remove dead copper, pour order 343): 99.477,47.926 99.477,47.403 104.898,47.403 129.54,72.045 129.54,79.756 129.794,80.01 135.763,80.01 137.16,78.613 148.354,78.613 148.354,81.407 132.358,81.407 132.334,81.383 129.643,81.383 128.778,80.518 128.778,72.146 104.558,47.926
PVDD on Mid-Layer 2 "MID-LAYER_2_PVDD_P335" (solid, remove dead copper, pour order 335): 94.833,61.971 95.315,61.971 95.315,62.453 95.319,62.458 91.714,66.062 91.563,66.062 86.345,71.281 48.388,71.281 40.154,63.047 40.154,60.904 39.735,60.485 26.343,60.485 24.776,58.917 18.868,58.917 18.868,60.631 18.962,60.631 19.641,61.311 20.727,61.311 20.727,60.585 20.926,60.387 20.926,59.409 24.446,59.409 26.012,60.975 39.268,60.975 39.483,61.189 39.483,63.272 48.104,71.894 87.056,71.894 93.195,65.755 97.038,61.911 97.038,60.001 94.581,60.001 94.581,61.719
OUT12 on Mid-Layer 2 "MID-LAYER_2_OUT12_P337" (solid, remove dead copper, pour order 337): 101.409,44.251 101.409,43.747 106.832,43.747 116.2,53.114 148.68,53.114 148.68,55.989 132.246,55.989 130.513,54.256 116.528,54.256 106.52,44.249 106.519,44.251
OUT11 on Mid-Layer 2 "MID-LAYER_2_OUT11_P347" (solid, remove dead copper, pour order 347): 100.376,40.103 99.788,39.516 99.737,39.503 76.173,39.503 73.713,37.043 73.713,34.19 73.761,34.142 75.321,34.142 75.321,35.621 74.836,36.106 74.836,37.312 76.515,38.991 100.207,38.991 100.966,39.751 100.966,44.802 106.414,44.802 106.527,44.913 121.23,59.615 135.774,59.615 136.969,58.42 148.336,58.42 148.354,58.438 148.354,60.96 121.715,60.96 106.142,45.387 99.539,45.387 99.504,45.353 100.376,44.482
OUT10 on Mid-Layer 2 "MID-LAYER_2_OUT10_P154" (solid, remove dead copper, pour order 341): 136.969,68.58 135.536,67.147 135.536,67.056 126.36,67.048 105.551,46.239 99.484,46.239 99.46,45.726 105.869,45.726 125.675,65.531 125.674,65.532 148.336,65.532 148.336,68.58
OUT9 on Mid-Layer 2 "MID-LAYER_2_OUT9_P339" (solid, remove dead copper, pour order 339): 99.399,46.927 99.419,46.946 104.925,46.946 131.639,73.66 148.463,73.66 148.463,70.612 136.969,70.612 135.536,72.045 130.874,72.045 105.388,46.559 99.451,46.559
OUT7 on Mid-Layer 2 "MID-LAYER_2_OUT7_P345" (solid, remove dead copper, pour order 345): 99.298,48.016 100.269,48.987 104.544,48.987 128.143,72.586 128.143,80.772 131.128,83.757 148.209,83.757 148.209,86.487 132.334,86.487 127.254,81.407 127.254,72.771 103.973,49.49 103.973,49.402 99.685,49.402 98.856,48.573 98.856,48.016
OUT6 on Mid-Layer 2 "MID-LAYER_2_OUT6_P353" (solid, remove dead copper, pour order 353): 98.2,49.778 98.2,50.364 100.585,50.364 123.952,73.731 123.952,94.546 133.604,94.546 133.604,91.904 127.889,91.904 126.492,90.507 126.492,72.89 103.273,49.671 98.216,49.671
OUT4 on Mid-Layer 2 "MID-LAYER_2_OUT4_P351" (solid, remove dead copper, pour order 351): 100.016,51.439 101.073,52.495 101.073,52.526 100.084,53.514 100.072,53.712 100.072,91.618 104.708,91.618 105.562,92.472 105.562,94.844 95.86,94.844 95.86,91.904 97.237,90.526 97.237,51.855 96.871,51.855 96.843,51.827 96.95,51.72 96.95,51.439
OUT3 on Mid-Layer 2 "MID-LAYER_2_OUT3_P349" (solid, remove dead copper, pour order 349): 119.05,72.773 100.922,54.645 100.922,51.976 100.072,51.126 100.039,51.159 97.436,51.159 97.436,50.677 97.463,50.65 100.502,50.65 102.445,52.593 121.59,71.738 121.59,94.539 112.37,94.539 112.37,92.862 113.328,91.904 118.415,91.904 119.05,91.269
SHIELD_GND on Mid-Layer 2 "MID-LAYER_2_SHIELD_GND_P354" (solid, remove dead copper, pour order 354): 7.956,95.301 39.452,95.301 39.452,100.815 7.956,100.815
3V3_MCU on Mid-Layer 2 "MID-LAYER_2_3V3_MCU_P355" (solid, remove dead copper, pour order 355): 48.172,36.63 35.676,36.63 14.346,36.63 14.346,57.258 12.673,58.917 12.673,63.903 12.689,63.918 4.279,63.918 0.623,60.262 0.623,36.278 3.651,33.25 48.172,33.25
PVDD on Mid-Layer 2 "MID-LAYER_2_PVDD_P356" (solid, remove dead copper, pour order 356): 115.621,37.933 115.636,37.918 120.396,37.918 120.396,20.586 110.381,20.586 110.381,24.155 77.616,24.155 77.616,24.213 73.214,24.213 73.156,24.155 73.127,24.184 73.127,31.166 77.616,31.166 77.616,34.136 83.716,34.136 83.716,35.858 110.254,35.858 113.753,35.858 113.753,37.933
GND on Mid-Layer 2 "MID-LAYER_2_GND_P357" (solid, remove dead copper, pour order 357): 0.173,0.046 0.173,101.646 152.573,101.646 152.573,0.046
OUT3 on Bottom Layer "BOTTOM_LAYER_OUT3_P362" (solid, remove dead copper, pour order 362): 111.86,96.535 111.896,92.114 113.296,91.305 115.329,91.388 115.329,96.535
OUT6 on Bottom Layer "BOTTOM_LAYER_OUT6_P360" (solid, remove dead copper, pour order 360): 124.424,89.615 127.067,89.615 127.067,94.485 124.715,94.485 124.424,94.194
GND on Bottom Layer "BOTTOM_LAYER_GND_P365" (solid, remove dead copper, pour order 365): 0,101.298 152.098,101.298 152.4,101.6 152.4,0 0,0
OUT4 on Bottom Layer "BOTTOM_LAYER_OUT4_P359" (solid, remove dead copper, pour order 359): 95.783,94.853 95.751,92.384 96.26,92.149 99.121,92.149 99.121,96.187 95.752,96.187
GND on Mid-Layer 1 "MID-LAYER_1_GND_P333" (solid, remove dead copper, pour order 333): 0,0 0,101.6 152.4,101.6 152.202,101.402 152.4,101.204 152.4,0

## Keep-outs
Keep-Out Layer:
  lines w0.508: 0,0 0,15.58 0,23.855 0,91.1 0,101.6 152.4,101.6 152.4,0 0,0
  text ".Layer_Name" at 14.316,-21.806 h1.52

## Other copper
Top Layer:
  pour cut-out: 88.969,30.159 88.944,30.184 88.691,30.184 88.691,35.842 88.815,35.966 88.869,35.966
  pour cut-out: 99.27,28.461 101.448,28.461 101.604,28.617 101.604,30.551 102.428,30.551 102.779,30.2 102.779,19.753 102.74,19.753 102.662,19.675 99.913,22.425 99.913,27.403 100.081,27.571 99.354,28.298 99.354,28.405
  region net XDS_VCC: 29.073,19.801 29.657,19.801 30.851,19.801 30.851,19.953 30.826,19.979 29.073,19.979
  region net XDS_VCC: 31.004,24.576 29.073,24.576 29.073,24.779 31.004,24.779
  region net XDS_VCC: 31.004,23.789 29.073,23.789 29.073,23.992 29.124,23.992 31.004,23.992
  region net XDS_VCC: 29.073,16.194 29.632,16.194 32.35,16.194 32.35,16.88 32.35,16.778 32.197,16.778 29.073,16.778
  pour cut-out: 12.499,9.358 16.876,9.358 16.876,13.852 12.499,13.852
  region net XDS_VCC: 27.194,10.886 27.016,10.886 27.016,14.949 27.088,14.949 27.194,14.949 27.194,12.467
  pour cut-out: 29.505,11.241 18.812,11.241 18.812,13.349 18.989,13.527 29.48,13.527 29.505,13.502
  pour cut-out: 16.754,15.915 16.754,23.89 14.468,23.89 14.468,16.245 14.798,15.915
  pour cut-out: 30.318,13.832 32.098,13.832 32.173,13.908 32.172,13.909 32.172,26.634 31.994,26.811 30.191,26.811 29.845,26.466 29.845,14.152
  region net XDS_VCC: 23.612,11.976 23.612,14.01 23.409,14.01 23.409,11.976
  region net XDS_VCC: 15.535,20.588 15.535,20.792 18.151,20.792 18.151,20.614 18.151,20.588
  pour cut-out: 10.504,16.792 11.891,16.792 11.677,17.006 11.677,17.186 10.504,17.186
  region net XDS_VCC: 23.815,27.853 23.815,25.44 23.993,25.44 23.993,27.853
  region net XDS_VCC: 27.016,27.853 27.016,25.287 27.194,25.287 27.194,27.853
  region net XDS_VCC: 21.809,25.44 22.418,25.44 22.418,29.631 21.809,29.631
  pour cut-out: 30.038,28.386 30.038,26.946 29.691,26.634 20.945,26.634 20.945,28.97 29.708,28.97
  text ".Layer_Name" at 14.316,-21.806 h1.52
Mid-Layer 1:
  pour cut-out: 10.252,13.832 10.252,20.106 13.681,20.106 13.681,18.805 14.69,18.805 14.9,18.594 14.9,15.407 14.671,15.178 13.681,15.178 13.681,13.832
Mid-Layer 2:
  pour cut-out: 10.252,13.832 13.655,13.832 13.681,13.857 13.681,15.178 14.671,15.178 14.9,15.407 14.9,18.594 14.69,18.805 13.681,18.805 13.681,20.106 10.252,20.106
Bottom Layer:
  text ".Layer_Name" at 14.316,-21.806 h1.52

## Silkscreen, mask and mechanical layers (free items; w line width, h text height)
Top Overlay:
  drawing of 1272 lines, arcs and shapes, not listed
  text "HIGH / SIDE DRIVERS" at 134.708,90.745 h2.29
  text "OUT7" at 135.753,86.978 h2.54
  text "CANL" at 22.111,85.814 h0.76 r90
  text "CANH" at 25.51,85.814 h0.76 r90
  text "VCC2" at 39.182,84.05 h0.76
  text "VCC1" at 43.325,84.05 h0.76
  text "LIN" at 19.639,83.06 h0.76 r90
  text "8" at 139.372,81.138 h2.54
  text "HSS4" at 5.411,73.88 h0.76
  text "9" at 139.394,73.432 h2.54
  text "OUT4" at 99.818,73.135 h5.08 r90
  text "OUT2" at 65.122,73.096 h5.08 r90
  text "OUT1" at 72.178,72.967 h5.08 r90
  text "OUT3" at 121.705,72.617 h5.08 r90
  text "DRV8000-Q1" at 49.886,72.466 h2.03
  text "M0" at 37.341,71.845 h2.03
  text "HSS3" at 5.487,71.43 h0.76
  text "HS-OUT5" at 94.49,69.596 h5.08 r90
  text "HS-OUT6" at 128.224,69.596 h5.08 r90
  text "HSS2" at 5.564,69.092 h0.76
  text "HALF-BRIDGE DRIVERS" at 83.366,67.286 h2.29
  text "HSS1" at 5.64,66.635 h0.76
  text "GD_IN1" at 56.992,65.38 h3.05
  text "10" at 138.182,63.17 h2.54
  text "1" at 1.092,62.746 h0.76
  text "2" at 3.99,62.746 h0.76
  text "3" at 6.537,62.746 h0.76
  text "GD_IN2" at 56.947,61.803 h3.05
  text "Read  / User Guide / before use" at 118.378,61.473 h0.76
  text "WAKE" at 1.494,58.625 h0.76
  text "PWM1" at 57.128,58.1 h3.05
  text "11" at 138.262,55.72 h2.54
  text "nSCS" at 56.947,54.19 h3.05
  text "IPROPI/ / PWM2" at 74.635,51.351 h2.54
  text "SDI" at 56.992,50.035 h3.05
  text "OUT12" at 134.636,49.836 h2.54
  text "Caution / Hot Surface" at 105.185,47.535 h0.76
  text "SO" at 78.579,46.292 h2.54
  text "SDO" at 58.191,45.999 h3.05
  text "GND" at 138.182,45.786 h3.3
  text "MCU_STATUS" at 9.151,45.703 h0.51
  text "IPROPI/ PWM2" at 32.325,45.053 h2.03
  text "nFAULT" at 9.12,43.363 h0.51
  text "PVDD" at 114.219,42.883 h0.76
  text "SO" at 42.261,42.389 h2.29
  text "SCLK" at 57.224,41.872 h3.05
  text "GH1" at 112.659,40.927 h1.27
  text "3V3" at 8.897,40.774 h0.51
  text "GL1" at 103.624,40.486 h1.27
  text "GL2" at 98.702,39.878 h1.27
  text "ECDRV" at 68.532,39.742 h1.27
  text "GH_HS" at 74.499,39.62 h1.27
  text "DRVOFF" at 57.128,37.911 h3.05
  text "NRST" at 34.756,36.097 h2.03 r90
  text "SWDIO" at 36.799,36.097 h2.03 r90
  text "SWCLK" at 38.957,36.097 h2.03 r90
  text "RXD>>" at 15.833,35.828 h2.03 r90
  text "TXD <<" at 19.576,35.778 h2.03 r90
  text "GH2" at 83.899,35.526 h1.27
  text "GUI_STATUS" at 0.775,34.983 h0.51
  text "nSLEEP" at 57.87,34.955 h3.05
  text "Target" at 28.359,33.639 h1.14
  text "Debugger" at 27.93,31.452 h1.14
  text "H-BRIDGE" at 100.733,24.081 h3.3
  text "30 A" at 100.787,21.076 h3.3
  text "HEATER" at 79.266,18.325 h3.3
  text "EC" at 58.022,16.845 h3.3
  text "VBAT" at 135.452,14.376 h5.08
  text "MIRROR" at 54.725,13.469 h3.3
  text "4.5 V -35 V DC" at 133.278,11.949 h2.54
  text "MD133.PCB_Rev" at 124.363,1.956 h2.75
  text "DRV8003-Q1 EVM" at 35.934,1.335 h2.41
  text ".Layer_Name" at 14.316,-21.806 h1.52
Bottom Overlay:
  text "Caution / Hot Surface" at 110.459,47.577 h0.76
  text "GND" at 20.31,14.01 h1.27 r90
  text "ITMS" at 22.495,14.01 h1.27 r90
  text "ITCK" at 24.679,14.01 h1.27 r90
  text "ITDO" at 26.889,14.01 h1.27 r90
  text "ITDI" at 29.073,14.01 h1.27 r90
  text "IRSTN" at 31.308,14.01 h1.27 r90
  text "XDS_VCC" at 33.671,14.01 h1.27 r90
  text ".Layer_Name" at 14.316,-21.806 h1.52
Top Paste:
  text ".Layer_Name" at 14.316,-21.806 h1.52
Bottom Paste:
  text ".Layer_Name" at 14.316,-21.806 h1.52
Top Solder:
  text ".Layer_Name" at 14.316,-21.806 h1.52
  text ".Layer_Name" at 14.316,-21.806 h1.52
Bottom Solder:
  text ".Layer_Name" at 14.316,-21.806 h1.52
Drill Guide:
  text ".Layer_Name" at 14.316,-21.806 h1.52
M1 Board Outline:
  lines w0.254: 0,17.163 0,15.58 0,2.032 ccw(c2,2.032) 2,0.032 150.4,0 ccw(c150.4,2) 152.4,2 152.4,99.6 ccw(c150.4,99.6) 150.4,101.6 133.265,101.6 44.195,101.6 2.471,101.639 ccw(c2.471,99.168) 0,99.168 0,91.1 0,23.855
  text ".Layer_Name" at 14.316,-21.806 h1.52
M2 Board Dimensions:
  rectangle: -0.34,-6.985 2.835,-3.81
  rectangle: 2.835,-10.16 12.36,-6.985
  lines w0.178: -0.34,-6.985 25.06,-6.985 ; 2.835,-10.16 2.835,-3.81 ; 6.01,-10.16 6.01,-3.81 ; 12.36,-10.16 12.36,-3.81 ; 18.71,-10.16 18.71,-3.81 ; -0.34,-10.16 25.06,-10.16 25.06,-3.81 -0.34,-3.81 -0.34,-10.16
  text ".Layer_Name" at 14.316,-21.806 h1.52
M3 3D STEP Top:
  text ".Layer_Name" at 14.316,-21.806 h1.52
M4 3D STEP Bottom:
  text ".Layer_Name" at 14.316,-21.806 h1.52
M5 Assembly Top:
  lines w0.254: -7.757,-23.626 159.883,-23.626 ; -7.757,-18.462 159.934,-18.462 ; -7.757,-13.297 -7.757,-28.791 93.97,-28.791 159.934,-28.791 159.934,-13.297 -7.744,-13.297 -7.744,-28.791 32.274,-28.791 ; 54.854,-28.791 54.854,-13.297 ; 87.036,-18.462 87.036,-13.297 ; 108.372,-18.462 108.372,-13.297 ; 124.171,-28.956 124.171,-23.804
  text "COMPONENTS MARKED 'DNP' SHOULD NOT BE POPULATED." at 28.959,-8.09 h1.52
  text "ASSEMBLY VARIANT:" at 28.946,-11.024 h1.52
  text ".VariantName" at 55.261,-11.024 h1.52
  text "PCB VIEWED FROM TOP SIDE" at -6.144,-16.654 h1.52
  text "BOARD #:" at 56.759,-16.654 h1.52
  text ".PRJ_Number" at 70.615,-16.654 h1.52
  text "REV:" at 92.065,-16.654 h1.52
  text ".PCB_Rev" at 99.469,-16.654 h1.52
  text "SVN REV:" at 113.35,-16.654 h1.52
  text ".VersionControl_RevNumber" at 126.203,-16.654 h1.52
  text "TID #:" at 56.759,-21.819 h1.52
  text ".TID" at 70.615,-21.819 h1.52
  text "PLOT NAME =" at -6.144,-27.034 h1.52
  text ".plot_File_Name" at 14.316,-27.034 h1.52
  text "GENERATED    :" at 56.81,-27.034 h1.52
  text ".Print_Date" at 78.895,-27.034 h1.52
  text ".Print_Time" at 97.412,-27.034 h1.52
  text "TEXAS INSTRUMENTS" at 129.53,-27.034 h1.52
M6 Assembly Bottom:
  lines w0.254: -7.769,-18.474 159.921,-18.474 ; -7.719,-23.639 159.921,-23.639 ; 27.994,-28.969 27.994,-23.817 ; 43.793,-18.474 43.793,-13.31 ; 65.129,-18.474 65.129,-13.31 ; 97.31,-28.804 97.31,-13.31 ; 119.891,-28.804 159.909,-28.804 159.909,-13.31 -7.769,-13.31 -7.769,-28.804 58.194,-28.804 159.921,-28.804 159.921,-13.31
  text "COMPONENTS MARKED 'DNP' SHOULD NOT BE POPULATED." at 154.651,-8.077 h1.52
  text ".VersionControl_RevNumber" at 268.402,-9.474 h1.52
  text ".VariantName" at 128.133,-11.024 h1.52
  text "ASSEMBLY VARIANT:" at 154.524,-11.024 h1.52
  text "SVN REV:" at 38.814,-16.667 h1.52
  text ".PCB_Rev" at 52.695,-16.667 h1.52
  text "REV:" at 60.099,-16.667 h1.52
  text ".PRJ_Number" at 81.55,-16.667 h1.52
  text "BOARD #:" at 95.405,-16.667 h1.52
  text "PCB VIEWED FROM BOTTOM SIDE" at 158.308,-16.667 h1.52
  text ".TID" at 81.55,-21.831 h1.52
  text "TID #:" at 95.405,-21.831 h1.52
  text "TEXAS INSTRUMENTS" at 22.634,-27.047 h1.52
  text ".Print_Time" at 54.753,-27.047 h1.52
  text ".Print_Date" at 73.269,-27.047 h1.52
  text "GENERATED    :" at 95.355,-27.047 h1.52
  text ".plot_File_Name" at 137.849,-27.047 h1.52
  text "PLOT NAME =" at 158.308,-27.047 h1.52
M9 Title Sheet:
  drawing of 57 lines, arcs and shapes, not listed
  text "1" at 18.452,204.127 h1.78
  text "2" at 81.842,204.127 h1.78
  text "3" at 145.071,204.127 h1.78
  text "4" at 208.74,204.127 h1.78
  text "5" at 272.215,204.127 h1.78
  text "6" at 335.842,204.127 h1.78
  text "A" at -10.919,175.095 h1.78
  text "A" at 365.001,175.095 h1.78
  text "B" at -10.919,114.643 h1.78
  text "B" at 365.001,114.643 h1.78
  text "C" at -10.919,54.318 h1.78
  text "C" at 365.001,54.318 h1.78
  text "PROJECT TITLE:" at 287.785,7.048 h1.14
  text ".PRJ_Title" at 289.055,3.662 h1.78
  text "DESIGNED FOR:" at 287.785,-0.597 h1.14
  text ".PRJ_Customer" at 289.055,-4.153 h1.78
  text "D" at -10.919,-5.88 h1.78
  text "D" at 365.001,-5.88 h1.78
  text "FILE NAME:" at 287.785,-8.217 h1.14
  text ".PCB_File_Name_No_Path" at 289.055,-11.265 h1.78
  text "Texas Instruments (TI) and/or its licensors do not warrant the accuracy or completeness of this specification" at 161.56,-15.376 h1.14
  text "ENGINEER:" at 287.785,-15.583 h1.14
  text "LAYOUT BY:" at 326.012,-15.583 h1.14
  text "or any information contained therein. TI and/or its licensors do not warrant that this design will meet" at 160.417,-18.237 h1.14
  text ".PRJ_Engineer" at 289.055,-19.52 h1.78
  text ".PCB_Layout" at 327.295,-19.52 h1.78
  text "the specifications, will be suitable for your application or fit for any particular purpose, or will operate in" at 160.417,-21.099 h1.14
  text ".Layer_Name" at 14.316,-21.806 h1.52
  text "ALTIUM DESIGNER VERSION:" at 326.012,-23.457 h1.14
  text "an implementation. TI and/or its licensors do not warrant that the design is production worthy. You should" at 160.417,-23.961 h1.14
  text "completely validate and test your design implementation to confirm the system functionality for your application." at 161.56,-26.822 h1.14
  text ".print_Scale" at 289.055,-26.843 h1.78
  text ".Application_BuildNumber" at 327.295,-26.843 h1.78
  text "1" at 18.452,-32.093 h1.78
  text "2" at 81.842,-32.093 h1.78
  text "3" at 145.071,-32.093 h1.78
  text "4" at 208.74,-32.093 h1.78
  text "5" at 272.215,-32.093 h1.78
  text "6" at 335.842,-32.093 h1.78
